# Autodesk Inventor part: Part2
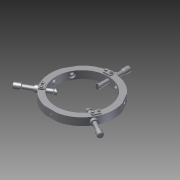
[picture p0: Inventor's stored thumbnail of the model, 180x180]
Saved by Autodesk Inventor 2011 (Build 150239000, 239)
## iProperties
Created: 2012-03
Part Number: Part2
Document SubType Name: Modeling
Designer: vadybininkas6
Density: 1 g/cm^3
Author: vadybininkas6
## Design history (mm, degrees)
feature "Base1"
body "Solid1"
